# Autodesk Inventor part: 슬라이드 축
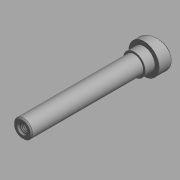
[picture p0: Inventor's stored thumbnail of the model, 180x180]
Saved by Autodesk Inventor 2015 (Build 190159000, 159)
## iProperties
Created: 2015-11
Part Number: 슬라이드 축
Document SubType Name: 모델링
Designer: mdu
Mass: 19.8501 g
Surface Area: 63.0734 cm^2
Volume: 19.8501 cm^3
Density: 1 g/cm^3
Material: 스테인리스강
Appearance: 기본값
변환 표준: STEP AP214IS
파일 이름: C:\Users\SeoGD\Desktop\?쒗뿕\異?stp
전처리기: Build: 253, Release: 2010 SP1 - Date: Wed 07/29/2009
전송 단위: 밀리미터
불확실성: 0.01
Author: mdu
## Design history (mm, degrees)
sketch "스케치1"
  geometry: L1 (0, 100)-(7.5, 100); L2 (7.5, 100)-(7.5, 0); L3 (7.5, 0)-(12.5, 0); L4 (12.5, 0)-(12.5, -17); L5 (12.5, -17)-(0, -17); L6 (0, -17)-(0, 100); 1 further point
  constraints: 12 end point, 2 parallel, 2 point on line, 1 perpendicular, 1 vertical
  dimensions: "d0" = 100 distance from line of L1 point (0, 0); "d1" = 15 diameter of L2 L6; "d2" = 25 diameter of L4 L6; "d3" = 17 distance of L3.end L4.end
revolve "회전1" sketch "스케치1" stored, may be unused: angle "d4" = 90 deg
sketch "스케치2"
  geometry: L1 (12.5, 0)-(12.5, -17) reference; L2 (-12.5, -17)-(12.5, -17) reference; L3 (-12.5, 0)-(-12.5, -17) reference; L4 (12.5, -5)-(-12.5, -11.699); L5 (-12.5, 0)-(12.5, 0) reference; 1 further point
  constraints: 2 end point, 2 point on line
  dimensions: "d5" = 75 deg angle of L1 L4; "d6" = 5 distance from line of L4.start L5
extrude "돌출1" cut sketch "스케치2" stored distance "d7" = 10; taper "d8" = 0 deg
chamfer "모따기1" distance "d9" = 1; stored, may be unused: second distance "d10" = 2, angle "d11" = 45 deg
fillet "모깎기1" dims "d12" = 0.5
hole "구멍1" diameter "d15" = 6.647; stored, may be unused: countersink angle "d19" = 90 deg, drill point angle "d21" = 118 deg; dims "d13" = 10, "d14" = 10, "d16" = 17, "d17" = 4, "d18" = 2, "d20" = 20
chamfer "모따기2" distance "d22" = 1; stored, may be unused: second distance "d23" = 2, angle "d24" = 45 deg
sketch "스케치3"
  geometry: C1 r 9 at (0, 0); 1 further point
  constraints: 1 centre point, 1 coincident
  dimensions: "d25" = 18 diameter of C1
extrude "돌출2" join sketch "스케치3" distance "d26" = 8; taper "d27" = 0 deg
node "솔리드1"
node "솔리드 본체"
node "곡면 본체"
node "솔리드2"
